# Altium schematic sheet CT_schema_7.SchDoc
size 391 x 238 mm
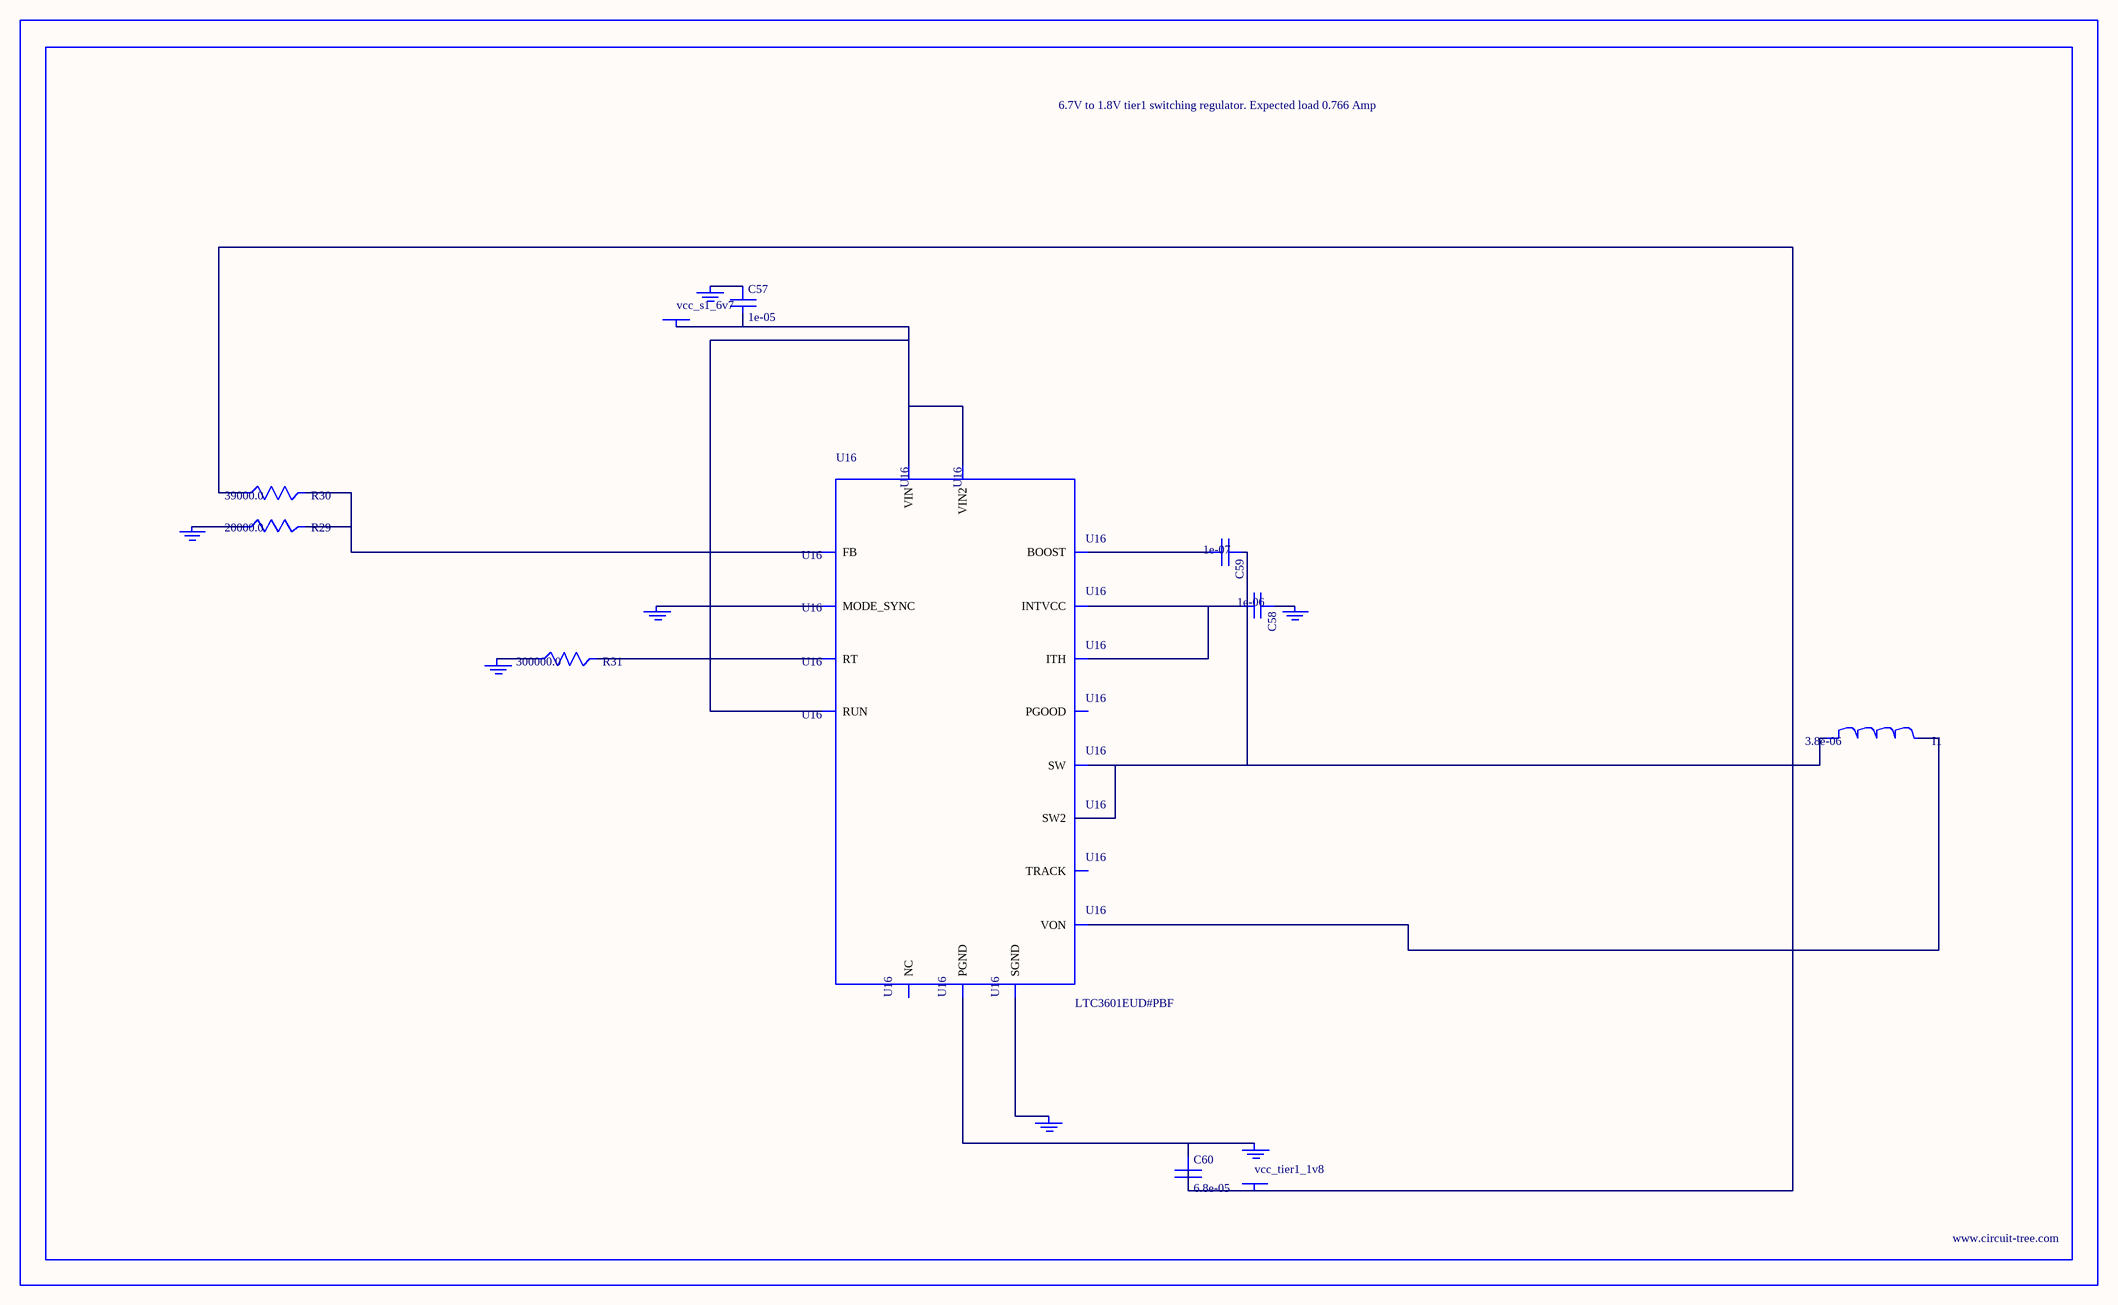
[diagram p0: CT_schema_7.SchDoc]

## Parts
BORDER6  (no value)
C57  1e-05  [C0805]
C58  1e-06  [C0603]
C59  1e-07  [C0402]
C60  6.8e-05  [2220]
GND_INSTANCE_6_0  (no value)
GND_INSTANCE_6_1  (no value)
GND_INSTANCE_6_2  (no value)
GND_INSTANCE_6_3  (no value)
GND_INSTANCE_6_4  (no value)
GND_INSTANCE_6_5  (no value)
GND_INSTANCE_6_6  (no value)
I1  3.8e-06  [DR1040]
POWER_INSTANCE_6_0  vcc_s1_6v7
POWER_INSTANCE_6_1  vcc_tier1_1v8
R29  20000.0  [R0603]
R30  39000.0  [R0603]
R31  300000.0  [R0603]
U16  LTC3601EUD#PBF  [QFN-16_EP]

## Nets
NetC57_1: C57.1 GND_INSTANCE_6_5.0(GND)
NetC57_2: C57.2 POWER_INSTANCE_6_0.0(PWR) U16.14(RUN) U16.15(VIN) U16.16(VIN2)
NetC58_1: C58.1 GND_INSTANCE_6_1.0(GND)
NetC58_2: C58.2 U16.7(INTVCC) U16.12(ITH)
NetC59_1: C59.1 I1.1 U16.3(SW) U16.4(SW2)
NetC59_2: C59.2 U16.6(BOOST)
NetC60_1: C60.1 GND_INSTANCE_6_6.0(GND) U16.17(PGND)
NetC60_2: C60.2 I1.2 POWER_INSTANCE_6_1.0(PWR) R30.1 U16.8(VON)
NetGND_INSTANCE_6_0_0: GND_INSTANCE_6_0.0(GND) U16.1(MODE_SYNC)
NetGND_INSTANCE_6_2_0: GND_INSTANCE_6_2.0(GND) U16.9(SGND)
NetGND_INSTANCE_6_3_0: GND_INSTANCE_6_3.0(GND) R31.1
NetGND_INSTANCE_6_4_0: GND_INSTANCE_6_4.0(GND) R29.1
NetR29_2: R29.2 R30.2 U16.11(FB)
NetR31_2: R31.2 U16.10(RT)

Not connected (* = marked no-connect by the designer): U16 2(PGOOD) 5(NC) 13(TRACK)

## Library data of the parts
BORDER6 = BORDER_PAGE6
C57 = C0805C106K8RACTU
C58 = C0603C105K3RACTU
C59 = C0402C104K3RACTU
C60 = C5750X5R1A686M
GND_INSTANCE_6_0-GND_INSTANCE_6_6 = GND
I1 = DR1040-3R8-R
POWER_INSTANCE_6_0 POWER_INSTANCE_6_1 = PWR
R29 = RC0603JR-0720KL
R30 = RC0603JR-0739KL
R31 = RC0603JR-07300KL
